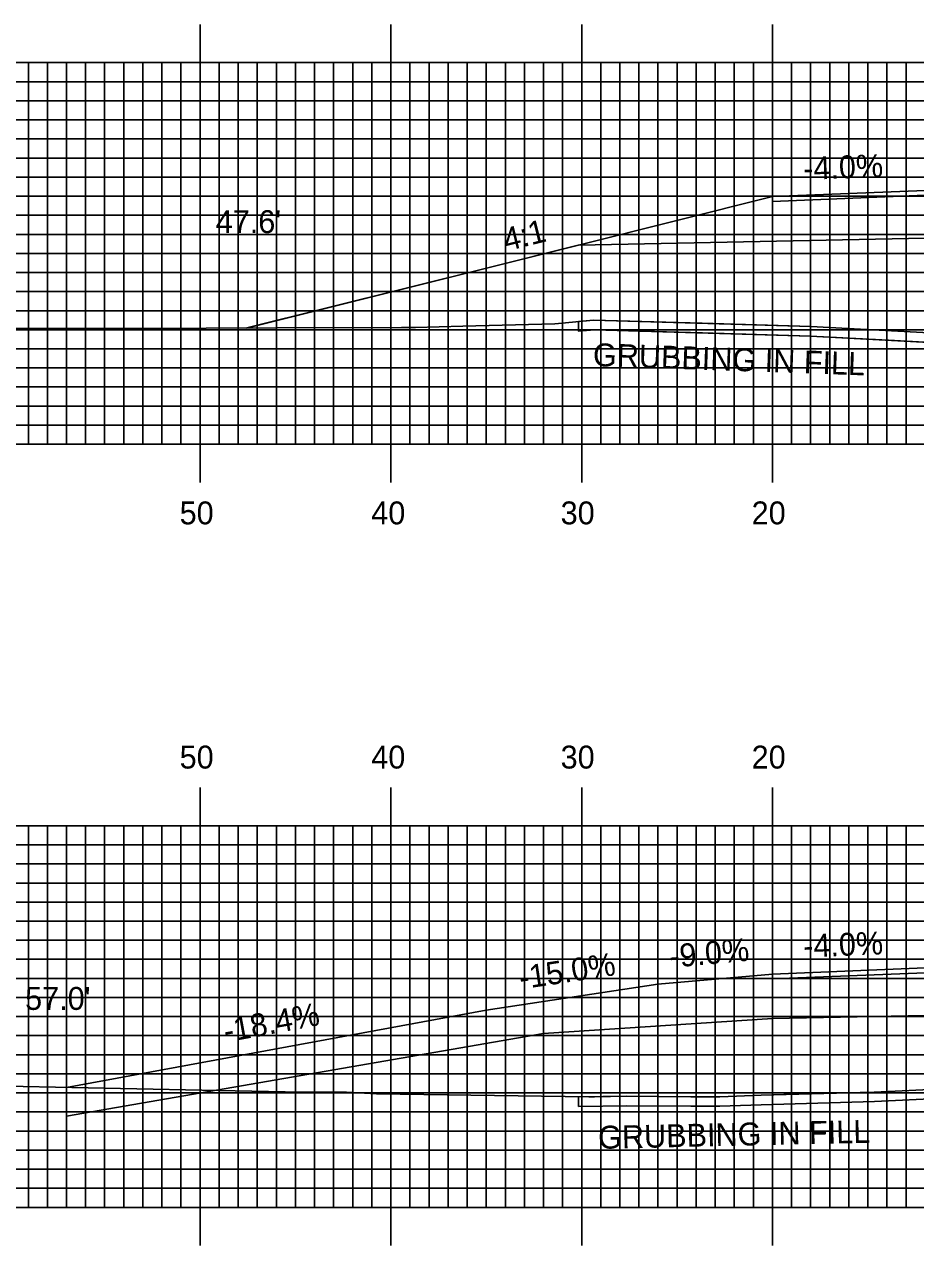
# Model space of a CAD drawing. Extents: x 1764546 to 1764889, y 442591 to 442811.
# Drawn here: x 1764652.1 to 1764698.8, y 442696.7 to 442760.7 of the extents above; entities that cross this region are included whole.
import ezdxf

# ---------------------------------------------------------------- set-up
doc = ezdxf.new("R2010")
doc.units = 0
for name, color, linetype in [('ANNOTATION', 7, 'Continuous'), ('D_Roadway_Centerline', 7, 'Continuous'), ('D_Roadway_Edge_Shoulder', 7, 'Continuous'), ('D_Roadway_SlopeLines', 7, 'Continuous'), ('D_Roadway_SubGrade', 7, 'Continuous'), ('D_Text_Standard', 7, 'Continuous'), ('GRUBBING IN FILL', 7, 'Continuous'), ('H_V ANNOTATION', 7, 'Continuous'), ('MAJOR', 7, 'Continuous'), ('MINOR', 7, 'Continuous'), ('S_Roadway_Centerline', 7, 'Continuous')]:
    doc.layers.add(name, color=color, linetype=linetype)

msp = doc.modelspace()

# ---------------------------------------------------------------- linework, layer by layer
at = {"layer": 'ANNOTATION'}
for p, q in [((1764685.344, 442710.356), (1764691.344, 442710.896)), ((1764691.345, 442708.556), (1764679.345, 442707.783)), ((1764654.345, 442703.452), (1764679.345, 442707.783))]:
    msp.add_line(p, q, dxfattribs=at)
msp.add_lwpolyline([(1764691.345, 442710.896), (1764685.344, 442710.356), (1764676.344, 442709.006), (1764654.345, 442704.952), (1764654.345, 442703.452)], dxfattribs=at)
at = {"layer": 'D_Roadway_Centerline'}
for points in [[(1764663.783, 442744.755), (1764663.79, 442744.757), (1764676.363, 442747.9), (1764681.169, 442749.102), (1764681.171, 442749.102), (1764681.173, 442749.103), (1764691.345, 442751.646), (1764699.345, 442751.966), (1764708.665, 442752.153), (1764711.345, 442752.206), (1764723.345, 442751.966), (1764723.348, 442751.966), (1764729.162, 442751.734), (1764731.343, 442751.646), (1764731.345, 442751.646), (1764733.645, 442751.071), (1764741.513, 442749.104), (1764741.519, 442749.102), (1764742.985, 442748.736), (1764743.345, 442748.646), (1764745.437, 442748.123), (1764754.594, 442745.833)], [(1764691.344, 442710.896), (1764691.344, 442710.896), (1764699.345, 442711.216), (1764711.345, 442711.456), (1764713.338, 442711.416), (1764723.345, 442711.216), (1764723.636, 442711.205), (1764731.345, 442710.896), (1764731.351, 442710.895), (1764739.47, 442708.865), (1764741.519, 442708.352), (1764742.426, 442708.126), (1764743.344, 442707.896), (1764743.346, 442707.896), (1764749.124, 442706.451), (1764755.477, 442704.863), (1764755.479, 442704.862)]]:
    msp.add_lwpolyline(points, dxfattribs=at)
at = {"layer": 'D_Roadway_Edge_Shoulder'}
for points in [[(1764699.345, 442751.966), (1764691.345, 442751.646), (1764691.345, 442751.396), (1764699.345, 442751.716)], [(1764699.345, 442711.216), (1764691.344, 442710.896), (1764691.344, 442710.646), (1764699.345, 442710.966)]]:
    msp.add_lwpolyline(points, close=True, dxfattribs=at)
at = {"layer": 'D_Roadway_SlopeLines'}
msp.add_lwpolyline([(1764691.345, 442751.646), (1764681.171, 442749.102), (1764663.783, 442744.755)], dxfattribs=at)
at = {"layer": 'D_Roadway_SubGrade'}
msp.add_lwpolyline([(1764691.345, 442751.396), (1764699.345, 442751.716), (1764699.345, 442751.299), (1764699.345, 442749.466), (1764681.171, 442749.102), (1764691.345, 442751.646)], close=True, dxfattribs=at)
msp.add_lwpolyline([(1764691.344, 442710.896), (1764691.344, 442710.646), (1764699.345, 442710.966), (1764699.345, 442710.549), (1764699.345, 442708.716), (1764691.345, 442708.556)], dxfattribs=at)
at = {"layer": 'GRUBBING IN FILL'}
for p, q in [((1764681.171, 442745.093), (1764681.973, 442745.169)), ((1764681.171, 442745.093), (1764681.973, 442745.169)), ((1764681.171, 442745.093), (1764681.171, 442744.591)), ((1764681.171, 442704.464), (1764681.171, 442703.956))]:
    msp.add_line(p, q, dxfattribs=at)
for points in [[(1764681.171, 442744.591), (1764682.024, 442744.667), (1764693.34, 442744.337), (1764701.508, 442743.899), (1764711.339, 442744.715), (1764718.68, 442745.32), (1764735.325, 442745.213), (1764736.726, 442745.197), (1764737.998, 442745.198), (1764741.518, 442745.227)], [(1764681.171, 442703.956), (1764683.72, 442703.985), (1764687.072, 442703.964), (1764688.587, 442703.963), (1764690.76, 442704.039), (1764696.695, 442704.211), (1764703.998, 442704.555), (1764704.738, 442704.565), (1764716.868, 442704.101), (1764723.686, 442704.085), (1764739.686, 442703.492), (1764740.033, 442703.491), (1764740.216, 442703.491), (1764741.519, 442703.54)]]:
    msp.add_lwpolyline(points, dxfattribs=at)
for points in [[(1764681.171, 442745.093), (1764681.973, 442745.169), (1764687.666, 442745.003), (1764693.36, 442744.837), (1764701.5, 442744.4), (1764711.345, 442745.217), (1764711.345, 442744.716), (1764701.508, 442743.899), (1764697.424, 442744.118), (1764693.34, 442744.337), (1764687.682, 442744.502), (1764682.024, 442744.667), (1764681.171, 442744.591)], [(1764681.171, 442745.093), (1764681.973, 442745.169), (1764687.666, 442745.003), (1764693.36, 442744.837), (1764701.5, 442744.4), (1764711.345, 442745.217), (1764711.345, 442744.716), (1764701.508, 442743.899), (1764697.424, 442744.118), (1764693.34, 442744.337), (1764687.682, 442744.502), (1764682.024, 442744.667), (1764681.171, 442744.591)], [(1764681.171, 442703.956), (1764681.171, 442704.464), (1764683.719, 442704.485), (1764685.396, 442704.475), (1764688.579, 442704.463), (1764690.744, 442704.539), (1764693.71, 442704.625), (1764696.676, 442704.711), (1764700.33, 442704.883), (1764704.744, 442705.065), (1764710.811, 442704.833), (1764711.345, 442704.812), (1764711.345, 442704.312), (1764710.803, 442704.333), (1764704.738, 442704.565), (1764703.998, 442704.555), (1764700.347, 442704.383), (1764696.695, 442704.211), (1764693.728, 442704.125), (1764690.76, 442704.039), (1764688.587, 442703.963), (1764687.072, 442703.964), (1764683.72, 442703.985)], [(1764681.171, 442703.956), (1764681.171, 442704.464), (1764683.719, 442704.485), (1764685.396, 442704.475), (1764688.579, 442704.463), (1764690.744, 442704.539), (1764693.71, 442704.625), (1764696.676, 442704.711), (1764700.33, 442704.883), (1764704.744, 442705.065), (1764710.811, 442704.833), (1764711.345, 442704.812), (1764711.345, 442704.312), (1764710.803, 442704.333), (1764704.738, 442704.565), (1764703.998, 442704.555), (1764700.347, 442704.383), (1764696.695, 442704.211), (1764693.728, 442704.125), (1764690.76, 442704.039), (1764688.587, 442703.963), (1764687.072, 442703.964), (1764683.72, 442703.985)]]:
    msp.add_lwpolyline(points, close=True, dxfattribs=at)
at = {"layer": 'MAJOR'}
for p, q in [((1764661.345, 442760.669), (1764661.345, 442758.665)), ((1764671.345, 442760.669), (1764671.345, 442758.665)), ((1764681.345, 442760.669), (1764681.345, 442758.665)), ((1764691.345, 442760.669), (1764691.345, 442758.665)), ((1764571.345, 442758.665), (1764851.345, 442758.665)), ((1764571.345, 442758.665), (1764851.345, 442758.665)), ((1764661.345, 442738.665), (1764661.345, 442758.665)), ((1764671.345, 442738.665), (1764671.345, 442758.665)), ((1764681.345, 442738.665), (1764681.345, 442758.665)), ((1764691.345, 442738.665), (1764691.345, 442758.665)), ((1764571.345, 442753.665), (1764851.345, 442753.665)), ((1764571.345, 442748.665), (1764851.345, 442748.665)), ((1764571.345, 442743.665), (1764851.345, 442743.665)), ((1764571.345, 442738.665), (1764851.345, 442738.665)), ((1764571.345, 442738.665), (1764851.345, 442738.665)), ((1764661.345, 442736.661), (1764661.345, 442738.665)), ((1764671.345, 442736.661), (1764671.345, 442738.665)), ((1764681.345, 442736.661), (1764681.345, 442738.665)), ((1764691.345, 442736.661), (1764691.345, 442738.665)), ((1764661.345, 442720.669), (1764661.345, 442718.665)), ((1764671.345, 442720.669), (1764671.345, 442718.665)), ((1764681.345, 442720.669), (1764681.345, 442718.665)), ((1764691.345, 442720.669), (1764691.345, 442718.665)), ((1764571.345, 442718.665), (1764851.345, 442718.665)), ((1764571.345, 442718.665), (1764851.345, 442718.665)), ((1764661.345, 442698.665), (1764661.345, 442718.665)), ((1764671.345, 442698.665), (1764671.345, 442718.665)), ((1764681.345, 442698.665), (1764681.345, 442718.665)), ((1764691.345, 442698.665), (1764691.345, 442718.665)), ((1764571.345, 442713.665), (1764851.345, 442713.665)), ((1764571.345, 442708.665), (1764851.345, 442708.665)), ((1764571.345, 442703.665), (1764851.345, 442703.665)), ((1764571.345, 442698.665), (1764851.345, 442698.665)), ((1764571.345, 442698.665), (1764851.345, 442698.665)), ((1764661.345, 442696.661), (1764661.345, 442698.665)), ((1764671.345, 442696.661), (1764671.345, 442698.665)), ((1764681.345, 442696.661), (1764681.345, 442698.665)), ((1764691.345, 442696.661), (1764691.345, 442698.665))]:
    msp.add_line(p, q, dxfattribs=at)
at = {"layer": 'MINOR'}
for p, q in [((1764652.345, 442738.665), (1764652.345, 442758.665)), ((1764653.345, 442738.665), (1764653.345, 442758.665)), ((1764654.345, 442738.665), (1764654.345, 442758.665)), ((1764655.345, 442738.665), (1764655.345, 442758.665)), ((1764656.345, 442738.665), (1764656.345, 442758.665)), ((1764657.345, 442738.665), (1764657.345, 442758.665)), ((1764658.345, 442738.665), (1764658.345, 442758.665)), ((1764659.345, 442738.665), (1764659.345, 442758.665)), ((1764660.345, 442738.665), (1764660.345, 442758.665)), ((1764662.345, 442738.665), (1764662.345, 442758.665)), ((1764663.345, 442738.665), (1764663.345, 442758.665)), ((1764664.345, 442738.665), (1764664.345, 442758.665)), ((1764665.345, 442738.665), (1764665.345, 442758.665)), ((1764666.345, 442738.665), (1764666.345, 442758.665)), ((1764667.345, 442738.665), (1764667.345, 442758.665)), ((1764668.345, 442738.665), (1764668.345, 442758.665)), ((1764669.345, 442738.665), (1764669.345, 442758.665)), ((1764670.345, 442738.665), (1764670.345, 442758.665)), ((1764672.345, 442738.665), (1764672.345, 442758.665)), ((1764673.345, 442738.665), (1764673.345, 442758.665)), ((1764674.345, 442738.665), (1764674.345, 442758.665)), ((1764675.345, 442738.665), (1764675.345, 442758.665)), ((1764676.345, 442738.665), (1764676.345, 442758.665)), ((1764677.345, 442738.665), (1764677.345, 442758.665)), ((1764678.345, 442738.665), (1764678.345, 442758.665)), ((1764679.345, 442738.665), (1764679.345, 442758.665)), ((1764680.345, 442738.665), (1764680.345, 442758.665)), ((1764682.345, 442738.665), (1764682.345, 442758.665)), ((1764683.345, 442738.665), (1764683.345, 442758.665)), ((1764684.345, 442738.665), (1764684.345, 442758.665)), ((1764685.345, 442738.665), (1764685.345, 442758.665)), ((1764686.345, 442738.665), (1764686.345, 442758.665)), ((1764687.345, 442738.665), (1764687.345, 442758.665)), ((1764688.345, 442738.665), (1764688.345, 442758.665)), ((1764689.345, 442738.665), (1764689.345, 442758.665)), ((1764690.345, 442738.665), (1764690.345, 442758.665)), ((1764692.345, 442738.665), (1764692.345, 442758.665)), ((1764693.345, 442738.665), (1764693.345, 442758.665)), ((1764694.345, 442738.665), (1764694.345, 442758.665)), ((1764695.345, 442738.665), (1764695.345, 442758.665)), ((1764696.345, 442738.665), (1764696.345, 442758.665)), ((1764697.345, 442738.665), (1764697.345, 442758.665)), ((1764698.345, 442738.665), (1764698.345, 442758.665)), ((1764571.345, 442757.665), (1764851.345, 442757.665)), ((1764571.345, 442756.665), (1764851.345, 442756.665)), ((1764571.345, 442755.665), (1764851.345, 442755.665)), ((1764571.345, 442754.665), (1764851.345, 442754.665)), ((1764571.345, 442752.665), (1764851.345, 442752.665)), ((1764571.345, 442751.665), (1764851.345, 442751.665)), ((1764571.345, 442750.665), (1764851.345, 442750.665)), ((1764571.345, 442749.665), (1764851.345, 442749.665)), ((1764571.345, 442747.665), (1764851.345, 442747.665)), ((1764571.345, 442746.665), (1764851.345, 442746.665)), ((1764571.345, 442745.665), (1764851.345, 442745.665)), ((1764571.345, 442744.665), (1764851.345, 442744.665)), ((1764571.345, 442742.665), (1764851.345, 442742.665)), ((1764571.345, 442741.665), (1764851.345, 442741.665)), ((1764571.345, 442740.665), (1764851.345, 442740.665)), ((1764571.345, 442739.665), (1764851.345, 442739.665)), ((1764652.345, 442698.665), (1764652.345, 442718.665)), ((1764653.345, 442698.665), (1764653.345, 442718.665)), ((1764654.345, 442698.665), (1764654.345, 442718.665)), ((1764655.345, 442698.665), (1764655.345, 442718.665)), ((1764656.345, 442698.665), (1764656.345, 442718.665)), ((1764657.345, 442698.665), (1764657.345, 442718.665)), ((1764658.345, 442698.665), (1764658.345, 442718.665)), ((1764659.345, 442698.665), (1764659.345, 442718.665)), ((1764660.345, 442698.665), (1764660.345, 442718.665)), ((1764662.345, 442698.665), (1764662.345, 442718.665)), ((1764663.345, 442698.665), (1764663.345, 442718.665)), ((1764664.345, 442698.665), (1764664.345, 442718.665)), ((1764665.345, 442698.665), (1764665.345, 442718.665)), ((1764666.345, 442698.665), (1764666.345, 442718.665)), ((1764667.345, 442698.665), (1764667.345, 442718.665)), ((1764668.345, 442698.665), (1764668.345, 442718.665)), ((1764669.345, 442698.665), (1764669.345, 442718.665)), ((1764670.345, 442698.665), (1764670.345, 442718.665)), ((1764672.345, 442698.665), (1764672.345, 442718.665)), ((1764673.345, 442698.665), (1764673.345, 442718.665)), ((1764674.345, 442698.665), (1764674.345, 442718.665)), ((1764675.345, 442698.665), (1764675.345, 442718.665)), ((1764676.345, 442698.665), (1764676.345, 442718.665)), ((1764677.345, 442698.665), (1764677.345, 442718.665)), ((1764678.345, 442698.665), (1764678.345, 442718.665)), ((1764679.345, 442698.665), (1764679.345, 442718.665)), ((1764680.345, 442698.665), (1764680.345, 442718.665)), ((1764682.345, 442698.665), (1764682.345, 442718.665)), ((1764683.345, 442698.665), (1764683.345, 442718.665)), ((1764684.345, 442698.665), (1764684.345, 442718.665)), ((1764685.345, 442698.665), (1764685.345, 442718.665)), ((1764686.345, 442698.665), (1764686.345, 442718.665)), ((1764687.345, 442698.665), (1764687.345, 442718.665)), ((1764688.345, 442698.665), (1764688.345, 442718.665)), ((1764689.345, 442698.665), (1764689.345, 442718.665)), ((1764690.345, 442698.665), (1764690.345, 442718.665)), ((1764692.345, 442698.665), (1764692.345, 442718.665)), ((1764693.345, 442698.665), (1764693.345, 442718.665)), ((1764694.345, 442698.665), (1764694.345, 442718.665)), ((1764695.345, 442698.665), (1764695.345, 442718.665)), ((1764696.345, 442698.665), (1764696.345, 442718.665)), ((1764697.345, 442698.665), (1764697.345, 442718.665)), ((1764698.345, 442698.665), (1764698.345, 442718.665)), ((1764571.345, 442717.665), (1764851.345, 442717.665)), ((1764571.345, 442716.665), (1764851.345, 442716.665)), ((1764571.345, 442715.665), (1764851.345, 442715.665)), ((1764571.345, 442714.665), (1764851.345, 442714.665)), ((1764571.345, 442712.665), (1764851.345, 442712.665)), ((1764571.345, 442711.665), (1764851.345, 442711.665)), ((1764571.345, 442710.665), (1764851.345, 442710.665)), ((1764571.345, 442709.665), (1764851.345, 442709.665)), ((1764571.345, 442707.665), (1764851.345, 442707.665)), ((1764571.345, 442706.665), (1764851.345, 442706.665)), ((1764571.345, 442705.665), (1764851.345, 442705.665)), ((1764571.345, 442704.665), (1764851.345, 442704.665)), ((1764571.345, 442702.665), (1764851.345, 442702.665)), ((1764571.345, 442701.665), (1764851.345, 442701.665)), ((1764571.345, 442700.665), (1764851.345, 442700.665)), ((1764571.345, 442699.665), (1764851.345, 442699.665))]:
    msp.add_line(p, q, dxfattribs=at)
at = {"layer": 'S_Roadway_Centerline'}
for points in [[(1764649.258, 442744.752), (1764653.503, 442744.733), (1764661.66, 442744.749), (1764665.332, 442744.759), (1764671.902, 442744.778), (1764672.63, 442744.776), (1764675.11, 442744.853), (1764679.93, 442744.977), (1764681.973, 442745.169), (1764693.36, 442744.837), (1764701.5, 442744.4), (1764711.298, 442745.213), (1764718.661, 442745.82), (1764735.33, 442745.713), (1764736.729, 442745.697), (1764737.995, 442745.698), (1764754.509, 442745.834), (1764760.706, 442745.784)], [(1764651.219, 442705.013), (1764661.44, 442704.811), (1764666.687, 442704.702), (1764669.021, 442704.705), (1764670.588, 442704.622), (1764681.727, 442704.456), (1764682.014, 442704.466), (1764683.719, 442704.485), (1764687.074, 442704.464), (1764688.579, 442704.463), (1764690.744, 442704.539), (1764696.676, 442704.711), (1764703.983, 442705.055), (1764704.744, 442705.065), (1764716.878, 442704.601), (1764723.696, 442704.585), (1764739.696, 442703.992), (1764740.035, 442703.991), (1764740.207, 442703.991), (1764740.709, 442704.01), (1764755.963, 442704.89), (1764758.482, 442704.826)]]:
    msp.add_lwpolyline(points, dxfattribs=at)

# ---------------------------------------------------------------- texts
at = {"layer": 'ANNOTATION'}
for s, rotation, p in [('-4.0%', 2.29053, (1764692.977, 442752.513)), ('4:1', 14.03945, (1764677.403, 442748.771)), ('-9.0%', 5.14276, (1764685.992, 442711.219)), ('-4.0%', 2.29053, (1764692.976, 442711.763)), ('-15.0%', 8.53089, (1764678.154, 442710.088)), ('-18.4%', 10.4427, (1764662.684, 442707.303))]:
    msp.add_text(s, height=1.2, rotation=rotation, dxfattribs=at).set_placement(p)
at = {"layer": 'D_Text_Standard'}
for s, p in [("47.6'", (1764662.165, 442749.732)), ("57.0'", (1764652.176, 442709.015))]:
    msp.add_text(s, height=1.2, dxfattribs=at).set_placement(p)
at = {"layer": 'GRUBBING IN FILL'}
for rotation, p in [(358.00778, (1764681.92, 442742.767)), (1.28373, (1764682.22, 442701.731))]:
    msp.add_text('GRUBBING IN FILL', height=1.2, rotation=rotation, dxfattribs=at).set_placement(p)
at = {"layer": 'H_V ANNOTATION'}
for s, p in [('50', (1764660.274, 442734.465)), ('40', (1764670.317, 442734.465)), ('30', (1764680.242, 442734.465)), ('20', (1764690.253, 442734.465)), ('50', (1764660.274, 442721.665)), ('40', (1764670.317, 442721.665)), ('30', (1764680.242, 442721.665)), ('20', (1764690.253, 442721.665))]:
    msp.add_text(s, height=1.2, dxfattribs=at).set_placement(p)

doc.saveas('drawing.dxf')
